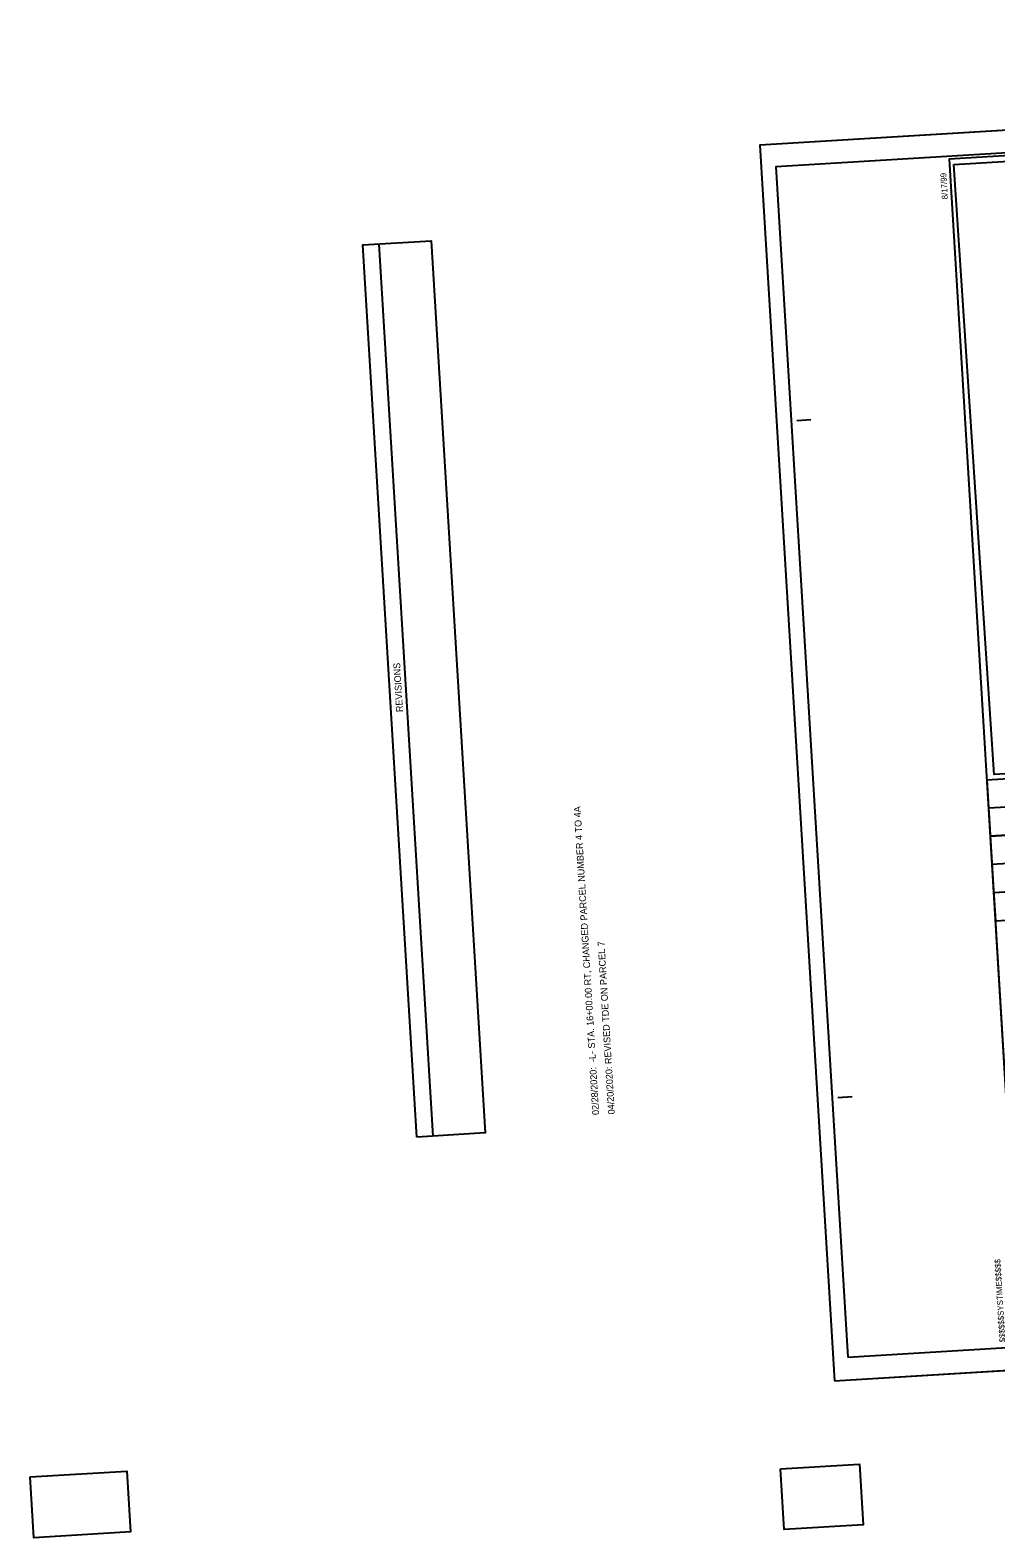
# Model space of a CAD drawing. Extents: x 2110128 to 2112690, y 669500 to 671339.
# Drawn here: x 2110128 to 2110982, y 669500 to 670834 of the extents above; entities that cross this region are included whole.
import ezdxf

# ---------------------------------------------------------------- set-up
doc = ezdxf.new("R2010")
doc.units = 0
for name, color, linetype in [('COGO Default Chain', 7, 'Continuous'), ('Exist Building', 7, 'Continuous'), ('Exist Other Culture Area Outline', 7, 'Continuous'), ('Exist Roads Curbs', 7, 'Continuous'), ('Exist Roads Curbs Text', 7, 'Continuous'), ('Exist Roads EOP Other Text', 7, 'Continuous'), ('Exist Roads Soil', 7, 'Continuous'), ('Exist Utilities Telephone Pole CELL', 7, 'Continuous'), ('Exist Utilities TV Hand Hole CELL', 7, 'Continuous'), ('Exist Utilities Water Fire Hydrant CELL', 7, 'Continuous'), ('Exist Utilities Water Test Hole SUE LOS A Text', 7, 'Continuous')]:
    doc.layers.add(name, color=color, linetype=linetype)

msp = doc.modelspace()

# ---------------------------------------------------------------- linework, layer by layer
at = {"layer": 'COGO Default Chain'}
for points in [[(2110127.7, 669554), (2110213.3, 669559.2), (2110216.6, 669505.3), (2110131, 669500.1)], [(2110791.5, 669561.1), (2110861.3, 669565.4), (2110864.6, 669511.6), (2110794.7, 669507.4)]]:
    msp.add_lwpolyline(points, close=True, dxfattribs=at)
at = {"layer": 'Exist Building'}
for points in [[(2110974, 670170.7), (2112471.3, 670261.5)], [(2112474.3, 670211.6), (2110977.1, 670120.8), (2110980.1, 670070.9), (2112477.3, 670161.7)], [(2110974, 670170.7), (2111002.8, 669696.6)]]:
    msp.add_lwpolyline(points, dxfattribs=at)
at = {"layer": 'Exist Other Culture Area Outline'}
for p, q in [((2110975.5, 670145.8), (2112472.8, 670236.5)), ((2112475.8, 670186.6), (2110978.6, 670095.9)), ((2110981.6, 670046), (2112478.8, 670136.7)), ((2110978.6, 670095.9), (2110981.6, 670046))]:
    msp.add_line(p, q, dxfattribs=at)
at = {"layer": 'Exist Roads Curbs'}
for p, q in [((2112453.6, 670834), (2110773.2, 670732.1)), ((2110773.2, 670732.1), (2110839.4, 669639.1)), ((2110839.4, 669639.1), (2112519.9, 669741))]:
    msp.add_line(p, q, dxfattribs=at)
at = {"layer": 'Exist Roads Curbs Text'}
for p, q in [((2110806, 670488.6), (2110818.5, 670489.4)), ((2110842.3, 669889.7), (2110854.8, 669890.5))]:
    msp.add_line(p, q, dxfattribs=at)
msp.add_lwpolyline([(2112438, 670810.5), (2110940.8, 670719.7), (2111004.3, 669671.6), (2112501.5, 669762.4)], close=True, dxfattribs=at)
at = {"layer": 'Exist Roads EOP Other Text'}
msp.add_lwpolyline([(2110851.2, 669659.9), (2112514.2, 669760.7), (2112450.3, 670813.7), (2110787.4, 670712.9)], close=True, dxfattribs=at)
at = {"layer": 'Exist Utilities Telephone Pole CELL'}
msp.add_line((2110484.4, 669855.5), (2110436.6, 670644.7), dxfattribs=at)
msp.add_lwpolyline([(2110469.9, 669854.7), (2110422, 670643.9), (2110482.5, 670647.5), (2110530.3, 669858.3)], close=True, dxfattribs=at)
at = {"layer": 'Exist Utilities TV Hand Hole CELL'}
for p, q in [((2110974, 670170.7), (2112471.3, 670261.5)), ((2110977.1, 670120.8), (2112474.3, 670211.6)), ((2110980.1, 670070.9), (2112477.3, 670161.7))]:
    msp.add_line(p, q, dxfattribs=at)
at = {"layer": 'Exist Utilities Water Fire Hydrant CELL'}
msp.add_lwpolyline([(2110945, 670715.2), (2112189.1, 670790.6), (2112200.1, 670603.3), (2112399.7, 670615.4), (2112418.3, 670308.4), (2112421.1, 670262.7), (2110980.5, 670175.4)], close=True, dxfattribs=at)
at = {"layer": 'Exist Utilities Water Test Hole SUE LOS A Text'}
msp.add_lwpolyline([(2110839.4, 669639.1), (2112519.9, 669741), (2112453.6, 670834), (2110773.2, 670732.1)], close=True, dxfattribs=at)

# ---------------------------------------------------------------- texts
at = {"layer": 'Exist Roads Curbs Text'}
msp.add_text('8/17/99', height=5.25, rotation=93.4682, dxfattribs=at).set_placement((2110939.6, 670684.4))
at = {"layer": 'Exist Roads Soil'}
msp.add_text('$$$$$$SYSTIME$$$$$', height=5.25, rotation=93.4682, dxfattribs=at).set_placement((2110990.5, 669673.2))
at = {"layer": 'Exist Utilities Telephone Pole CELL'}
for s, p in [('REVISIONS', (2110457.6, 670230.8)), ('02/28/2020:  -L- STA. 16+00.00 RT, CHANGED PARCEL NUMBER 4 TO 4A                                                                ', (2110631.1, 669874.4)), ('04/20/2020: REVISED TDE ON PARCEL 7                                                                                             ', (2110645, 669874.9))]:
    msp.add_text(s, height=6, rotation=93.4682, dxfattribs=at).set_placement(p)

doc.saveas('drawing.dxf')
